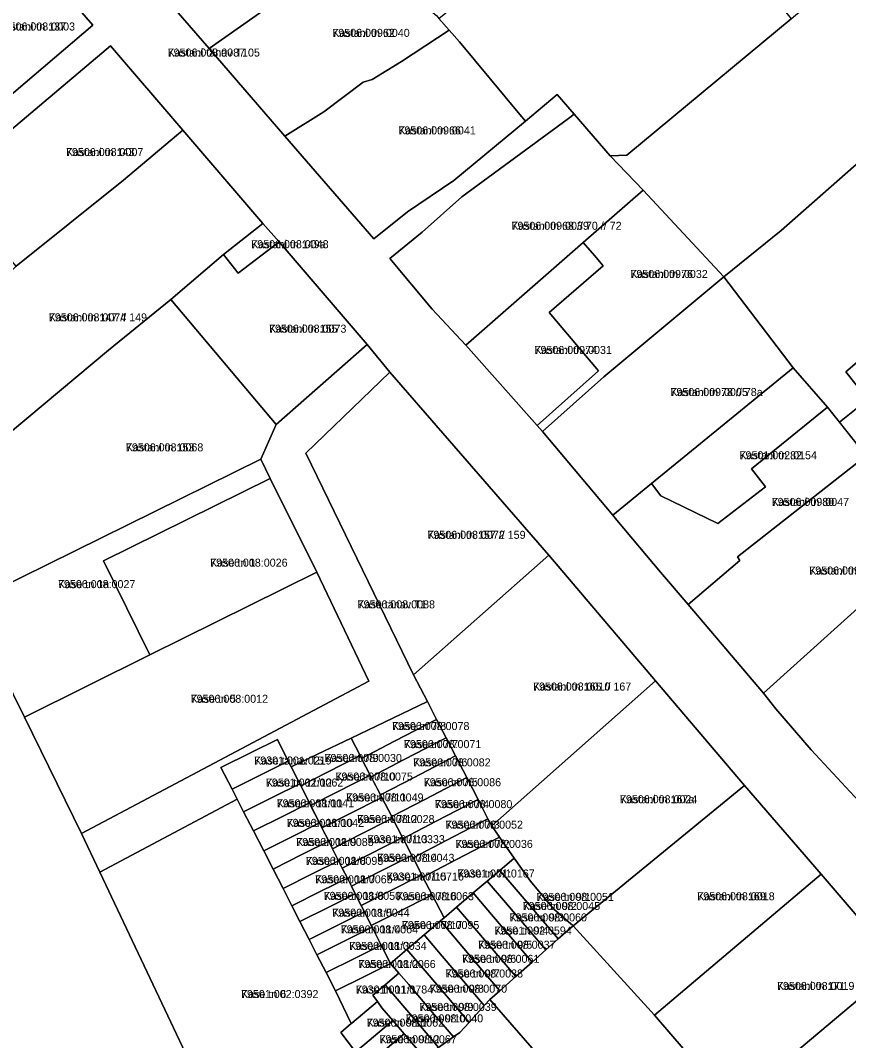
# Model space of a CAD drawing. Extents: x 643847 to 663718, y 6468443 to 6482775.
# Drawn here: x 658980.7 to 659135.9, y 6472833.9 to 6473025.1 of the extents above; entities that cross this region are included whole.
import ezdxf

# ---------------------------------------------------------------- set-up
doc = ezdxf.new("R2010")
doc.units = 0
for name, color, linetype in [('L_AADRESS', 7, 'Continuous'), ('PIIR', 7, 'Continuous'), ('TUNNUS', 7, 'Continuous')]:
    doc.layers.add(name, color=color, linetype=linetype)

msp = doc.modelspace()

# ---------------------------------------------------------------- linework, layer by layer
at = {"layer": 'PIIR'}
for points in [[(658827.03, 6473115.78), (658838.96, 6473101.24), (658844.72, 6473094.48), (658849.4, 6473089), (658835.12, 6473077.3), (658858.05, 6473052.71), (658863.9, 6473048.89), (658875.4, 6473058.55), (658892.98, 6473035.86), (658893.93, 6473034.64), (658907.6, 6473014.23), (658922.44, 6472991.84), (658934.89, 6472973.59), (658947.86, 6472954.59), (658948.45, 6472953.59), (658959.35, 6472935.31), (658960.8, 6472932.88), (658970.93, 6472915.87), (658981.5, 6472894.57), (658992.14, 6472872.73), (658995.57, 6472865.47), (659014.95, 6472824.56)], [(659160.01, 6472831.12), (659145.35, 6472848.08), (659130.72, 6472865.11), (659116.35, 6472881.76), (659099.69, 6472901.36), (659079.69, 6472924.88), (659049.93, 6472959.21), (659045.67, 6472964.39), (659029.19, 6472983.58), (659026.15, 6472987.07), (659011.13, 6473004.54), (658997.61, 6473020.32), (658969.3, 6472996.48), (658963.89, 6472998.37), (658972.21, 6473005.47), (658994.25, 6473024.24), (658979.81, 6473040.96)], [(659002.75, 6473035.22), (659016.06, 6473019.83), (659030.25, 6473003.44), (659046.9, 6472984.19), (659053.23, 6472989.26), (659061.93, 6472995.13), (659075.33, 6473006.24), (659081.29, 6473011.21), (659084.48, 6473007.51), (659083.39, 6473006.71), (659063.43, 6472992.03), (659056, 6472985.42), (659049.93, 6472980.5), (659057.83, 6472970.97), (659064.16, 6472964.23), (659077.51, 6472949.19), (659078.5, 6472948.06), (659091.7, 6472932.4), (659092.48, 6472931.43), (659100.66, 6472921.71), (659105.83, 6472915.66), (659119.91, 6472899.03), (659122.23, 6472896.09), (659128.85, 6472888.45), (659141.04, 6472875.28)]]:
    msp.add_lwpolyline(points, dxfattribs=at)
for points in [[(659081.29, 6473011.21), (659075.33, 6473006.24), (659074.29, 6473007.5), (659062.95, 6473021.08), (659061.03, 6473023.28), (659059.12, 6473025.46), (659099.23, 6473058.01), (659103.19, 6473052.95), (659117.49, 6473035.03), (659125.13, 6473025.41), (659094.35, 6472999.83), (659091.21, 6472999.7), (659084.48, 6473007.51)], [(659155.16, 6473051.86), (659162.9, 6473044.51), (659179.98, 6473023.32), (659180.07, 6473013.96), (659180.34, 6472985.85), (659177.07, 6472982.42), (659166.2, 6472985.69), (659147.71, 6473007.27), (659123.22, 6472985.75), (659112.47, 6472977.03), (659097.41, 6472993.3), (659091.21, 6472999.7), (659094.35, 6472999.83), (659125.13, 6473025.41), (659147.51, 6473044.37)], [(659002.75, 6473035.22), (659013.97, 6473045.15), (659025.79, 6473030.86), (659027.8, 6473028.1), (659016.06, 6473019.83)], [(658994.25, 6473024.24), (658972.21, 6473005.47), (658958.05, 6473021.77), (658972.87, 6473033.89), (658972.45, 6473034.95), (658979.81, 6473040.96)], [(659030.25, 6473003.44), (659016.06, 6473019.83), (659027.8, 6473028.1), (659045.53, 6473040.6), (659056.45, 6473027.84), (659058.74, 6473025.96), (659059.12, 6473025.46), (659061.03, 6473023.28), (659052.1, 6473017.41), (659046.6, 6473014.02), (659044.94, 6473013.54), (659037.55, 6473008)], [(659046.9, 6472984.19), (659030.25, 6473003.44), (659037.55, 6473008), (659044.94, 6473013.54), (659046.6, 6473014.02), (659052.1, 6473017.41), (659061.03, 6473023.28), (659062.95, 6473021.08), (659074.29, 6473007.5), (659075.33, 6473006.24), (659061.93, 6472995.13), (659053.23, 6472989.26)], [(659011.13, 6473004.54), (659000.02, 6472995.15), (658979.91, 6472979.04), (658976.99, 6472982.5), (658969.3, 6472996.48), (658997.61, 6473020.32)], [(659064.16, 6472964.23), (659057.83, 6472970.97), (659049.93, 6472980.5), (659056, 6472985.42), (659063.43, 6472992.03), (659083.39, 6473006.71), (659084.48, 6473007.51), (659091.21, 6472999.7), (659097.41, 6472993.3), (659086.17, 6472983.46)], [(659147.71, 6473007.27), (659166.2, 6472985.69), (659135.36, 6472959.26), (659139.49, 6472954.05), (659134.14, 6472949.81), (659131.92, 6472952.61), (659125.48, 6472959.98), (659112.47, 6472977.03), (659123.22, 6472985.75)], [(659011.13, 6473004.54), (659026.15, 6472987.07), (659018.73, 6472981.22), (659008.88, 6472972.83), (658997.24, 6472963.28), (658960.8, 6472932.88), (658959.35, 6472935.31), (658948.45, 6472953.59), (658972.3, 6472971.84), (658979.91, 6472979.04), (659000.02, 6472995.15)], [(659077.51, 6472949.19), (659088.99, 6472959.45), (659079.77, 6472970.37), (659089.89, 6472979.09), (659088.28, 6472981.06), (659086.17, 6472983.46), (659097.41, 6472993.3), (659112.47, 6472977.03), (659089.99, 6472958.34), (659078.5, 6472948.06)], [(659026.15, 6472987.07), (659029.19, 6472983.58), (659021.49, 6472977.77), (659018.73, 6472981.22)], [(659166.2, 6472985.69), (659177.07, 6472982.42), (659176.53, 6472958.37), (659157.92, 6472944.08), (659156.37, 6472943.05), (659146.01, 6472934.94), (659141.31, 6472940.59), (659139.17, 6472943.51), (659134.14, 6472949.81), (659139.49, 6472954.05), (659135.36, 6472959.26)], [(659029.19, 6472983.58), (659045.67, 6472964.39), (659028.65, 6472949.41), (659008.88, 6472972.83), (659018.73, 6472981.22), (659021.49, 6472977.77)], [(659077.51, 6472949.19), (659064.16, 6472964.23), (659086.17, 6472983.46), (659088.28, 6472981.06), (659089.89, 6472979.09), (659079.77, 6472970.37), (659088.99, 6472959.45)], [(659078.5, 6472948.06), (659089.99, 6472958.34), (659112.47, 6472977.03), (659125.48, 6472959.98), (659098.96, 6472938.32), (659091.7, 6472932.4)], [(659008.88, 6472972.83), (659028.65, 6472949.41), (659025.72, 6472942.87), (658970.93, 6472915.87), (658960.8, 6472932.88), (658997.24, 6472963.28)], [(659028.65, 6472949.41), (659045.67, 6472964.39), (659049.93, 6472959.21), (659034.21, 6472943.98), (659054.33, 6472902.5), (659056.95, 6472897.45), (659048.95, 6472893.62), (659042.67, 6472890.62), (659036.37, 6472887.61), (659031.42, 6472885.24), (659030.89, 6472886.3), (659028.85, 6472890.33), (659023.96, 6472887.93), (659018.27, 6472885.12), (659020.36, 6472881.02), (659021.31, 6472879.18), (658995.57, 6472865.47), (658992.14, 6472872.73), (659045.97, 6472901.28), (659036.22, 6472921.74), (659027.53, 6472939.26), (659025.72, 6472942.87)], [(659120.28, 6472937.71), (659111.4, 6472930.82), (659100.72, 6472936.04), (659098.96, 6472938.32), (659125.48, 6472959.98), (659131.92, 6472952.61), (659117.67, 6472941.08)], [(659049.93, 6472959.21), (659079.69, 6472924.88), (659054.33, 6472902.5), (659034.21, 6472943.98)], [(659100.66, 6472921.71), (659092.48, 6472931.43), (659091.7, 6472932.4), (659098.96, 6472938.32), (659100.72, 6472936.04), (659111.4, 6472930.82), (659120.28, 6472937.71), (659117.67, 6472941.08), (659131.92, 6472952.61), (659139.17, 6472943.51), (659115.07, 6472924.57), (659115.52, 6472923.89), (659105.83, 6472915.66)], [(659025.72, 6472942.87), (659027.53, 6472939.26), (658996.25, 6472923.84), (659004.94, 6472906.21), (658981.5, 6472894.57), (658970.93, 6472915.87)], [(659119.91, 6472899.03), (659105.83, 6472915.66), (659115.52, 6472923.89), (659115.07, 6472924.57), (659139.17, 6472943.51), (659141.31, 6472940.59), (659146.01, 6472934.94), (659151.9, 6472927.93), (659140.08, 6472917.19)], [(659027.53, 6472939.26), (659036.22, 6472921.74), (659004.94, 6472906.21), (658996.25, 6472923.84)], [(659099.69, 6472901.36), (659069.01, 6472874.17), (659068.31, 6472875.5), (659066.45, 6472879.1), (659064.32, 6472883.22), (659062.21, 6472887.29), (659060.46, 6472890.66), (659058.67, 6472894.13), (659056.95, 6472897.45), (659054.33, 6472902.5), (659079.69, 6472924.88)], [(659045.97, 6472901.28), (658992.14, 6472872.73), (658981.5, 6472894.57), (659004.94, 6472906.21), (659036.22, 6472921.74)], [(659141.04, 6472875.28), (659128.85, 6472888.45), (659122.23, 6472896.09), (659119.91, 6472899.03), (659140.08, 6472917.19), (659155.72, 6472896.95), (659160.47, 6472891.61)], [(659116.35, 6472881.76), (659084.28, 6472855.46), (659080.57, 6472858.61), (659076.28, 6472863.83), (659073.24, 6472868.15), (659070.49, 6472872.06), (659069.01, 6472874.17), (659099.69, 6472901.36)], [(659042.67, 6472890.62), (659048.95, 6472893.62), (659056.95, 6472897.45), (659058.67, 6472894.13), (659050.81, 6472890.03), (659044.64, 6472886.81), (659044.37, 6472887.33)], [(659044.64, 6472886.81), (659050.81, 6472890.03), (659058.67, 6472894.13), (659060.46, 6472890.66), (659052.61, 6472886.58), (659046.43, 6472883.36), (659046.26, 6472883.69)], [(659018.27, 6472885.12), (659023.96, 6472887.93), (659028.85, 6472890.33), (659030.89, 6472886.3), (659026, 6472883.85), (659020.36, 6472881.02)], [(659031.42, 6472885.24), (659036.37, 6472887.61), (659042.67, 6472890.62), (659044.37, 6472887.33), (659038.12, 6472884.16), (659033.24, 6472881.68), (659033.04, 6472882.07)], [(659046.43, 6472883.36), (659052.61, 6472886.58), (659060.46, 6472890.66), (659062.21, 6472887.29), (659054.37, 6472883.2), (659048.18, 6472879.97)], [(659033.24, 6472881.68), (659038.12, 6472884.16), (659044.37, 6472887.33), (659044.64, 6472886.81), (659046.26, 6472883.69), (659039.98, 6472880.51), (659035.08, 6472878.02), (659034.85, 6472878.48)], [(659048.18, 6472879.97), (659054.37, 6472883.2), (659062.21, 6472887.29), (659064.32, 6472883.22), (659056.49, 6472879.14), (659050.28, 6472875.91), (659048.42, 6472879.5)], [(659026, 6472883.85), (659030.89, 6472886.3), (659031.42, 6472885.24), (659033.04, 6472882.07), (659028.14, 6472879.62), (659022.53, 6472876.79), (659021.31, 6472879.18), (659020.36, 6472881.02)], [(659035.08, 6472878.02), (659039.98, 6472880.51), (659046.26, 6472883.69), (659048.18, 6472879.97), (659048.42, 6472879.5), (659042.11, 6472876.3), (659037.21, 6472873.81), (659036.75, 6472874.72)], [(659022.53, 6472876.79), (659028.14, 6472879.62), (659033.04, 6472882.07), (659033.24, 6472881.68), (659034.85, 6472878.48), (659029.95, 6472876.02), (659024.38, 6472873.22)], [(659050.28, 6472875.91), (659056.49, 6472879.14), (659064.32, 6472883.22), (659066.45, 6472879.1), (659058.63, 6472875.03), (659052.41, 6472871.79), (659052.3, 6472871.99), (659050.43, 6472875.61)], [(659130.72, 6472865.11), (659099.5, 6472838.69), (659084.28, 6472855.46), (659116.35, 6472881.76)], [(658995.57, 6472865.47), (659021.31, 6472879.18), (659022.53, 6472876.79), (659024.38, 6472873.22), (659026.29, 6472869.49), (659028.04, 6472866.09), (659029.91, 6472862.43), (659031.57, 6472859.18), (659033.08, 6472856.23), (659034.79, 6472852.88), (659036.27, 6472849.99), (659037.97, 6472846.68), (659039.74, 6472843.24), (659042.7, 6472837.12), (659040.76, 6472835.47), (659043.49, 6472831.83), (659045.48, 6472829.2), (659048.51, 6472825.15), (659043.48, 6472821.6), (659022.75, 6472804.22), (659014.95, 6472824.56)], [(659024.38, 6472873.22), (659029.95, 6472876.02), (659034.85, 6472878.48), (659036.75, 6472874.72), (659031.83, 6472872.26), (659026.29, 6472869.49)], [(659037.21, 6472873.81), (659042.11, 6472876.3), (659048.42, 6472879.5), (659050.28, 6472875.91), (659050.43, 6472875.61), (659044.1, 6472872.4), (659039.18, 6472869.89), (659038.46, 6472871.31)], [(659052.41, 6472871.79), (659058.63, 6472875.03), (659066.45, 6472879.1), (659068.31, 6472875.5), (659060.5, 6472871.44), (659054.27, 6472868.19), (659054.03, 6472868.65)], [(659026.29, 6472869.49), (659031.83, 6472872.26), (659036.75, 6472874.72), (659037.21, 6472873.81), (659038.46, 6472871.31), (659033.54, 6472868.84), (659028.04, 6472866.09)], [(659039.18, 6472869.89), (659044.1, 6472872.4), (659050.43, 6472875.61), (659052.3, 6472871.99), (659045.95, 6472868.75), (659041.02, 6472866.25), (659040.32, 6472867.64)], [(659054.27, 6472868.19), (659060.5, 6472871.44), (659068.31, 6472875.5), (659069.01, 6472874.17), (659070.49, 6472872.06), (659062.38, 6472867.84), (659056.13, 6472864.58), (659055.91, 6472864.99)], [(659041.02, 6472866.25), (659045.95, 6472868.75), (659052.3, 6472871.99), (659052.41, 6472871.79), (659054.03, 6472868.65), (659047.65, 6472865.41), (659042.71, 6472862.9), (659041.96, 6472864.39)], [(659057.83, 6472861.28), (659056.13, 6472864.58), (659062.38, 6472867.84), (659070.49, 6472872.06), (659073.24, 6472868.15), (659070.52, 6472865.84), (659068.18, 6472863.84), (659065.54, 6472861.6), (659062.44, 6472858.96), (659060.07, 6472856.94)], [(659028.04, 6472866.09), (659033.54, 6472868.84), (659038.46, 6472871.31), (659039.18, 6472869.89), (659040.32, 6472867.64), (659035.39, 6472865.17), (659029.91, 6472862.43)], [(659049.51, 6472861.74), (659044.57, 6472859.22), (659043.45, 6472861.43), (659042.71, 6472862.9), (659047.65, 6472865.41), (659054.03, 6472868.65), (659054.27, 6472868.19), (659055.91, 6472864.99)], [(659070.52, 6472865.84), (659073.24, 6472868.15), (659076.28, 6472863.83), (659080.57, 6472858.61), (659084.28, 6472855.46), (659081.47, 6472852.98), (659078.32, 6472856.69), (659073.94, 6472861.83)], [(659029.91, 6472862.43), (659035.39, 6472865.17), (659040.32, 6472867.64), (659041.02, 6472866.25), (659041.96, 6472864.39), (659037.01, 6472861.91), (659031.57, 6472859.18)], [(659031.57, 6472859.18), (659037.01, 6472861.91), (659041.96, 6472864.39), (659042.71, 6472862.9), (659043.45, 6472861.43), (659038.5, 6472858.94), (659033.08, 6472856.23)], [(659044.57, 6472859.22), (659049.51, 6472861.74), (659055.91, 6472864.99), (659056.13, 6472864.58), (659057.83, 6472861.28), (659051.4, 6472858.01), (659046.45, 6472855.49), (659045.15, 6472858.07)], [(659068.18, 6472863.84), (659070.52, 6472865.84), (659073.94, 6472861.83), (659078.32, 6472856.69), (659081.47, 6472852.98), (659079.16, 6472850.93), (659075.96, 6472854.69), (659071.59, 6472859.83)], [(659145.35, 6472848.08), (659114.06, 6472821.75), (659099.5, 6472838.69), (659130.72, 6472865.11)], [(659065.54, 6472861.6), (659068.18, 6472863.84), (659071.59, 6472859.83), (659075.96, 6472854.69), (659079.16, 6472850.93), (659076.57, 6472848.63), (659073.33, 6472852.45), (659068.96, 6472857.59)], [(659033.08, 6472856.23), (659038.5, 6472858.94), (659043.45, 6472861.43), (659044.57, 6472859.22), (659045.15, 6472858.07), (659040.19, 6472855.58), (659034.79, 6472852.88)], [(659046.45, 6472855.49), (659051.4, 6472858.01), (659057.83, 6472861.28), (659060.07, 6472856.94), (659059.39, 6472856.36), (659056.34, 6472853.76), (659053.12, 6472851.02), (659050.03, 6472848.4), (659048.28, 6472851.84), (659046.61, 6472855.17)], [(659065.86, 6472854.95), (659062.44, 6472858.96), (659065.54, 6472861.6), (659068.96, 6472857.59), (659073.33, 6472852.45), (659076.57, 6472848.63), (659073.53, 6472845.95), (659070.24, 6472849.81)], [(659059.39, 6472856.36), (659060.07, 6472856.94), (659062.44, 6472858.96), (659065.86, 6472854.95), (659070.24, 6472849.81), (659073.53, 6472845.95), (659070.53, 6472843.28), (659067.18, 6472847.21), (659062.8, 6472852.35)], [(659034.79, 6472852.88), (659040.19, 6472855.58), (659045.15, 6472858.07), (659046.45, 6472855.49), (659046.61, 6472855.17), (659041.64, 6472852.68), (659036.27, 6472849.99)], [(659036.27, 6472849.99), (659041.64, 6472852.68), (659046.61, 6472855.17), (659048.28, 6472851.84), (659043.31, 6472849.35), (659037.97, 6472846.68)], [(659056.34, 6472853.76), (659059.39, 6472856.36), (659062.8, 6472852.35), (659067.18, 6472847.21), (659070.53, 6472843.28), (659068.64, 6472841.61), (659067.62, 6472840.5), (659064.12, 6472844.61), (659059.75, 6472849.75)], [(659112.23, 6472791.11), (659109.04, 6472794.82), (659090.65, 6472816.18), (659077.81, 6472831.11), (659068.64, 6472841.61), (659070.53, 6472843.28), (659073.53, 6472845.95), (659076.57, 6472848.63), (659079.16, 6472850.93), (659081.47, 6472852.98), (659084.28, 6472855.46), (659099.5, 6472838.69), (659114.06, 6472821.75), (659128.23, 6472805.13)], [(659053.12, 6472851.02), (659056.34, 6472853.76), (659059.75, 6472849.75), (659064.12, 6472844.61), (659067.62, 6472840.5), (659064.76, 6472837.35), (659060.9, 6472841.87), (659056.53, 6472847.01)], [(659037.97, 6472846.68), (659043.31, 6472849.35), (659048.28, 6472851.84), (659050.03, 6472848.4), (659045.04, 6472845.89), (659039.74, 6472843.24)], [(659050.03, 6472848.4), (659053.12, 6472851.02), (659056.53, 6472847.01), (659060.9, 6472841.87), (659064.76, 6472837.35), (659063.04, 6472835.47), (659061.84, 6472834.61), (659057.86, 6472839.28), (659053.49, 6472844.42), (659051.6, 6472846.59)], [(659042.82, 6472837.23), (659042.7, 6472837.12), (659039.74, 6472843.24), (659045.04, 6472845.89), (659050.03, 6472848.4), (659051.6, 6472846.59), (659049.04, 6472844.4), (659046.75, 6472842.47), (659047.59, 6472841.28)], [(659160.01, 6472831.12), (659128.23, 6472805.13), (659114.06, 6472821.75), (659145.35, 6472848.08)], [(659049.04, 6472844.4), (659051.6, 6472846.59), (659053.49, 6472844.42), (659057.86, 6472839.28), (659061.84, 6472834.61), (659059.05, 6472832.64), (659057.08, 6472834.96), (659055.27, 6472837.08), (659050.9, 6472842.22)], [(659046.75, 6472842.47), (659049.04, 6472844.4), (659050.9, 6472842.22), (659055.27, 6472837.08), (659057.08, 6472834.96), (659059.05, 6472832.64), (659056.37, 6472830.74), (659054.73, 6472832.68), (659052.59, 6472835.19), (659050.47, 6472837.68), (659048.42, 6472840.1), (659047.59, 6472841.28)], [(659090.65, 6472816.18), (659109.04, 6472794.82), (659112.23, 6472791.11), (659096.09, 6472777.35), (659092.85, 6472781.11), (659074.47, 6472802.46), (659054.07, 6472829.11), (659056.37, 6472830.74), (659059.05, 6472832.64), (659061.84, 6472834.61), (659063.04, 6472835.47), (659064.76, 6472837.35), (659067.62, 6472840.5), (659068.64, 6472841.61), (659077.81, 6472831.11)], [(659047.59, 6472841.28), (659048.42, 6472840.1), (659050.47, 6472837.68), (659045.21, 6472833.28), (659043.49, 6472831.83), (659040.76, 6472835.47), (659042.7, 6472837.12), (659042.82, 6472837.23)], [(659050.47, 6472837.68), (659052.59, 6472835.19), (659047.2, 6472830.63), (659045.48, 6472829.2), (659043.49, 6472831.83), (659045.21, 6472833.28)], [(659052.59, 6472835.19), (659054.73, 6472832.68), (659056.37, 6472830.74), (659054.07, 6472829.11), (659048.51, 6472825.15), (659045.48, 6472829.2), (659047.2, 6472830.63)]]:
    msp.add_lwpolyline(points, close=True, dxfattribs=at)

# ---------------------------------------------------------------- texts
at = {"layer": 'L_AADRESS'}
for s, p in [('Kastani tn 137', (658976.43, 6473023.21)), ('Kastani tn 62', (659039.14, 6473022.02)), ('Kastani tänav T105', (659008.29, 6473018.33)), ('Kastani tn 66', (659051.52, 6473003.74)), ('Kastani tn 143', (658989.24, 6472999.68)), ('Kastani tn 68 // 70 // 72', (659072.71, 6472985.87)), ('Kastani tn 149a', (659023.95, 6472982.42)), ('Kastani tn 76', (659094.99, 6472976.84)), ('Kastani tn 147 // 149', (658986.03, 6472968.71)), ('Kastani tn 155', (659027.28, 6472966.59)), ('Kastani tn 74', (659077.02, 6472962.6)), ('Kastani tn 78 // 78a', (659102.49, 6472954.71)), ('Kastani tn 153', (659000.47, 6472944.35)), ('Kastani tn 82', (659115.44, 6472942.87)), ('Kastani tn 80', (659121.46, 6472934.13)), ('Kastani tn 157 // 159', (659056.95, 6472927.96)), ('Kase tn 1', (659016.26, 6472922.74)), ('Kastani tn 86', (659128.5, 6472921.27)), ('Kase tn 1a', (658987.74, 6472918.72)), ('Kase tänav T1', (659043.88, 6472914.93)), ('Kastani tn 165 // 167', (659076.75, 6472899.53)), ('Kase tn 5', (659012.6, 6472897.24)), ('Kase tn 7/8', (659050.33, 6472892.13)), ('Kase tn 7/7', (659052.56, 6472888.74)), ('Kase tn 7/9', (659037.68, 6472886.15)), ('Kase tänav T5', (659024.52, 6472885.67)), ('Kase tn 7/6', (659054.3, 6472885.32)), ('Kase tn 7/10', (659039.73, 6472882.67)), ('Kase tn 11/12', (659026.7, 6472881.54)), ('Kase tn 7/5', (659056.26, 6472881.6)), ('Kase tn 7/11', (659041.73, 6472878.75)), ('Kastani tn 167a', (659093.03, 6472878.41)), ('Kase tn 11/11', (659028.71, 6472877.65)), ('Kase tn 7/4', (659058.37, 6472877.5)), ('Kase tn 7/12', (659043.79, 6472874.7)), ('Kase tn 11/10', (659030.59, 6472873.99)), ('Kase tn 7/3', (659060.36, 6472873.65)), ('Kase tn 11/9', (659032.39, 6472870.4)), ('Kase tn 7/13', (659045.72, 6472870.93)), ('Kase tn 7/2', (659062.21, 6472870.04)), ('Kase tn 11/8', (659034.19, 6472866.87)), ('Kase tn 7/14', (659047.52, 6472867.44)), ('Kase tn 11/7', (659035.94, 6472863.41)), ('Kase tn 7/15', (659049.29, 6472863.93)), ('Kase tn 7/1', (659062.56, 6472864.5)), ('Kase tn 11/6', (659037.52, 6472860.31)), ('Kase tn 7/16', (659051.18, 6472860.24)), ('Kase tn 9/1', (659077.4, 6472860.12)), ('Kastani tn 169', (659107.52, 6472860.23)), ('Kase tn 11/5', (659039.13, 6472857.15)), ('Kase tn 9/2', (659074.82, 6472858.41)), ('Kase tn 9/3', (659072.35, 6472856.27)), ('Kase tn 11/4', (659040.71, 6472854.03)), ('Kase tn 7/17', (659052.19, 6472854.84)), ('Kase tn 9/4', (659069.5, 6472853.81)), ('Kase tn 11/3', (659042.3, 6472850.93)), ('Kase tn 9/5', (659066.46, 6472851.15)), ('Kase tn 11/2', (659044.01, 6472847.54)), ('Kase tn 9/6', (659063.44, 6472848.51)), ('Kase tn 9/7', (659060.37, 6472845.76)), ('Kase tn 6', (659022.04, 6472841.91)), ('Kase tn 11/1', (659043.53, 6472842.76)), ('Kase tn 9/8', (659057.39, 6472842.91)), ('Kastani tn 171', (659122.46, 6472843.43)), ('Kase tn 9/9', (659055.44, 6472839.5)), ('Kase tn 9/11', (659045.58, 6472836.55)), ('Kase tn 9/10', (659052.9, 6472837.35)), ('Kase tn 9/12', (659047.96, 6472833.44))]:
    msp.add_text(s, height=1.5, dxfattribs=at).set_placement(p)
at = {"layer": 'TUNNUS'}
for s, p in [('79506:008:0003', (658976.43, 6473023.21)), ('79506:009:0040', (659039.14, 6473022.02)), ('79506:008:0087', (659008.29, 6473018.33)), ('79506:009:0041', (659051.52, 6473003.74)), ('79506:008:0007', (658989.24, 6472999.68)), ('79506:009:0039', (659072.71, 6472985.87)), ('79506:008:0048', (659023.95, 6472982.42)), ('79506:009:0032', (659094.99, 6472976.84)), ('79506:008:0074', (658986.03, 6472968.71)), ('79506:008:0073', (659027.28, 6472966.59)), ('79506:009:0031', (659077.02, 6472962.6)), ('79506:009:0005', (659102.49, 6472954.71)), ('79506:008:0068', (659000.47, 6472944.35)), ('79501:002:0154', (659115.44, 6472942.87)), ('79506:009:0047', (659121.46, 6472934.13)), ('79506:008:0072', (659056.95, 6472927.96)), ('79506:008:0026', (659016.26, 6472922.74)), ('79506:009:0035', (659128.5, 6472921.27)), ('79506:008:0027', (658987.74, 6472918.72)), ('79506:008:0088', (659043.88, 6472914.93)), ('79506:008:0010', (659076.75, 6472899.53)), ('79506:008:0012', (659012.6, 6472897.24)), ('79506:008:0078', (659050.33, 6472892.13)), ('79506:008:0071', (659052.56, 6472888.74)), ('79506:008:0030', (659037.68, 6472886.15)), ('79301:001:0219', (659024.52, 6472885.67)), ('79506:008:0082', (659054.3, 6472885.32)), ('79506:008:0075', (659039.73, 6472882.67)), ('79501:002:0062', (659026.7, 6472881.54)), ('79506:008:0086', (659056.26, 6472881.6)), ('79506:008:0049', (659041.73, 6472878.75)), ('79506:008:0024', (659093.03, 6472878.41)), ('79506:008:0041', (659028.71, 6472877.65)), ('79506:008:0080', (659058.37, 6472877.5)), ('79506:008:0028', (659043.79, 6472874.7)), ('79506:008:0042', (659030.59, 6472873.99)), ('79506:008:0052', (659060.36, 6472873.65)), ('79301:001:0333', (659045.72, 6472870.93)), ('79506:008:0083', (659032.39, 6472870.4)), ('79506:008:0036', (659062.21, 6472870.04)), ('79506:008:0093', (659034.19, 6472866.87)), ('79506:008:0043', (659047.52, 6472867.44)), ('79506:008:0065', (659035.94, 6472863.41)), ('79301:001:0716', (659049.29, 6472863.93)), ('79301:001:0167', (659062.56, 6472864.5)), ('79506:008:0050', (659037.52, 6472860.31)), ('79506:008:0063', (659051.18, 6472860.24)), ('79506:008:0051', (659077.4, 6472860.12)), ('79506:008:0018', (659107.52, 6472860.23)), ('79506:008:0044', (659039.13, 6472857.15)), ('79506:008:0045', (659074.82, 6472858.41)), ('79506:008:0060', (659072.35, 6472856.27)), ('79506:008:0064', (659040.71, 6472854.03)), ('79506:008:0095', (659052.19, 6472854.84)), ('79501:002:0594', (659069.5, 6472853.81)), ('79506:008:0034', (659042.3, 6472850.93)), ('79506:008:0037', (659066.46, 6472851.15)), ('79506:008:0066', (659044.01, 6472847.54)), ('79506:008:0061', (659063.44, 6472848.51)), ('79506:008:0038', (659060.37, 6472845.76)), ('79501:002:0392', (659022.04, 6472841.91)), ('79301:001:0784', (659043.53, 6472842.76)), ('79506:008:0070', (659057.39, 6472842.91)), ('79506:008:0019', (659122.46, 6472843.43)), ('79506:008:0039', (659055.44, 6472839.5)), ('79506:008:0062', (659045.58, 6472836.55)), ('79506:008:0040', (659052.9, 6472837.35)), ('79506:008:0067', (659047.96, 6472833.44))]:
    msp.add_text(s, height=1.5, dxfattribs=at).set_placement(p)

doc.saveas('drawing.dxf')
